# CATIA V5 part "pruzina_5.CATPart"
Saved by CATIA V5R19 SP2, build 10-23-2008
Part number: Pruzina delka 18mm
Bounding box of the stored display mesh (mm): x -8 to 8, y -8 to 8, z 0 to 18
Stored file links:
  D:\DURATEC\pruzina_5.CATPart
  D:\DURATEC\pruzina_1.CATPart
  D:\DURATEC\Pohyb pruziny.CATProduct
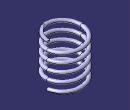
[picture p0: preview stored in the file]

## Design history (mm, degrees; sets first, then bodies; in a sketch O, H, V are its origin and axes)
External parameters (linked from other documents)
  `External.Delka pruziny` = 18 mm
  `External.Pocet zavitu` = 5
  `External.Vnitrni prumer pruziny` = 13 mm
  `External.Prumer dratu` = 1.5 mm
Set1
  Plane1: type Normal, Curve {line type PtDir, Direction (0, 0, 1), Start 0, End 18 {= `External.Delka pruziny`}, RefPoint {point type Coord, X 0, Y 0, Z 0}}, RefPoint vertex of Plane1
  Sketch1 on zx-plane, origin (0, 0, 0), H (-1, 0, 0), V (0, 0, 1)
    line L1 (6.5, 17) -> (6.5, 12)
    construction line L2 (6.5, 12) -> (-6.5, 12)
    line L3 (-6.5, 12) -> (-6.5, 17)
    construction line L4 (-6.5, 17) -> (6.5, 17)
    reference intersected line E1 through (0, 18) direction (-1, 0) from Plane1
    distance L3 L1 = 13 {= `External.Vnitrni prumer pruziny`}
    length L1 = 5
    distance L4 E1 = 1
    vertical: L1 V, L3 V
    horizontal: L2 H, L4 H
    equidistance: L1 L3 O
  Line1: type PtDir, Direction (0, 0, 1), Start 0, End 18 {= `External.Delka pruziny`}, RefPoint {point type Coord, X 0, Y 0, Z 0}
Body1 "Pruzina" (main body)
  Helix1: Pitch 3.6 {= `External.Delka pruziny` /`External.Pocet zavitu`}, TaperAngle 0, Height 18 {= Plane1.End}, Direction {line type PtDir, Direction (0, 0, 1), Start 0, End 18 {= `External.Delka pruziny`}, RefPoint {point type Coord, X 0, Y 0, Z 0}}, RefPoint {point type Coord, X 7.25 {= `External.Vnitrni prumer pruziny` /2+`External.Prumer dratu` /2}, Y 0, Z 0}
  Sketch2 on zx-plane, origin (0, 0, 0), H (-1, 0, 0), V (0, 0, 1)
    circle A1 centre (-7.25, 0) radius 0.75
    point P1 (-7.25, 0)
    reference projected point E1 (-7.25, 0) from vertex of Helix1
    radius A1 = 0.75 {= `External.Prumer dratu` /2}
    distance V A1 = 6.5 (reference)
    distance V A1 = 8 (reference)
    coincidence: P1 E1
  Rib1: profile Sketch2, centre curve Helix1
  Split1: SplitPlane xy-plane
  Split2: SplitPlane Plane1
